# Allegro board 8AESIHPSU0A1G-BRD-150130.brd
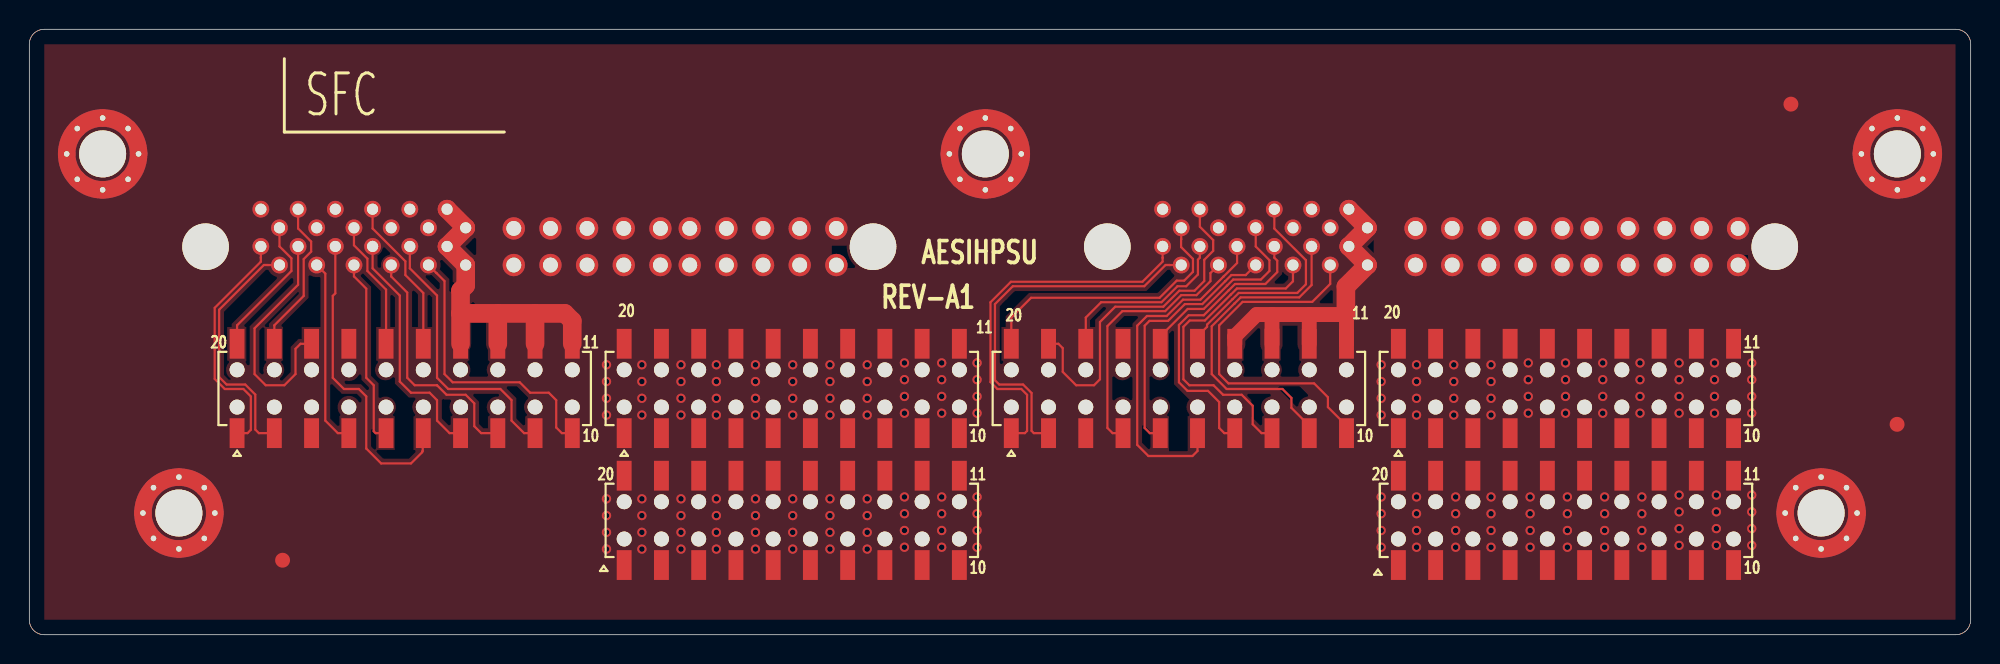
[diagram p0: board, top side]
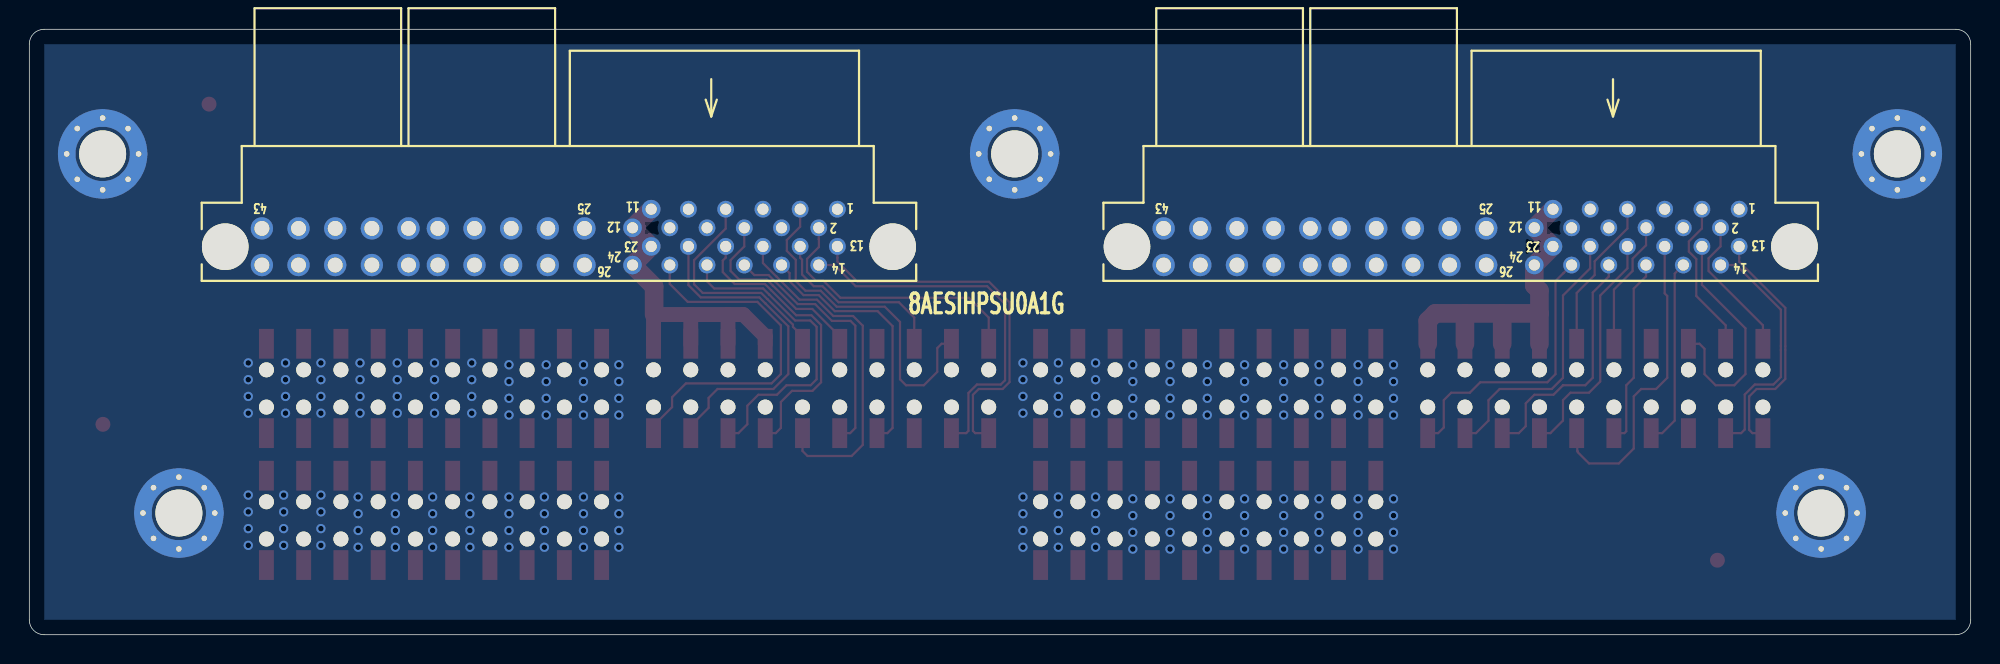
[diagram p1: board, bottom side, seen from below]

Outline 132.4 x 41.3 mm; copper layers: TOP, L2_GND1, L3_GND2, BOTTOM. Coordinates in mm from the lower left corner of the outline.
Outline path: 0,40.3 0,1 arc(0.29,0.29) 1,0 131.4,0 arc(132.11,0.29) 132.4,1 132.4,40.3 arc(132.11,41.01) 131.4,41.3 1,41.3 arc(0.29,41.01) 0,40.3

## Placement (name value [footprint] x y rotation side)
A1  3.5mm_8via  [A126_JNPR]  10.2 8.3 0 top
A2  3.5mm_8via  [A126_JNPR]  65.2 32.8 0 top
A3  3.5mm_8via  [A126_JNPR]  122.2 8.3 0 top
A4  3.5mm_8via  [A126_JNPR]  5 32.8 0 top
A5  3.5mm_8via  [A126_JNPR]  127.4 32.8 0 top
B1  Optics  [B]  17.27 5.08 0 top
B2  Optics  [B]  120.14 36.2 0 top
B3  Optics  [B]  127.38 14.35 0 top
JP1  2135_210MG0CUNT1  [IC_JP2X10_2P54_SMD]  14.17 15.53 0 top
JP2  2135_210MG0CUNT1  [IC_JP2X10_2P54_SMD]  40.57 15.53 0 top
JP3  2135_210MG0CUNT1  [IC_JP2X10_2P54_SMD]  66.97 15.53 0 top
JP4  2135_210MG0CUNT1  [IC_JP2X10_2P54_SMD]  93.37 15.53 0 top
JP5  2135_210MG0CUNT1  [IC_JP2X10_2P54_SMD]  40.57 6.53 0 top
JP6  2135_210MG0CUNT1  [IC_JP2X10_2P54_SMD]  93.37 6.53 0 top
NOREF  -  []  2.66 3.3 0 top
NOREF#2  -  []  0 0 0 top
NOREF#3  ***  []  23.21 2.18 0 top
NOREF#4  -  []  17.39 34.29 0 top
NOREF#5  -  []  58.79 21.84 0 top
NOREF#6  -  []  140.79 48.51 0 top
P1  SD45984_4343  [SD45984_4343_JNPR]  119.04 26.47 0 bottom
P2  SD45984_4343  [SD45984_4343_JNPR]  57.54 26.47 0 bottom

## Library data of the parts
A1-A5 = SCREW HOLE_6: Tolerance: ***; User Part Number: ***; room: SCREW
B1-B3 = Optics_solder_0: Tolerance: ***; User Part Number: ***
JP1-JP6 = HEADER_0: Tolerance: ***; User Part Number: ***
P1 P2 = SD45984_0: Tolerance: ***; User Part Number: ***

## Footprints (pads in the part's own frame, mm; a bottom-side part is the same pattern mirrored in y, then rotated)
A126_JNPR
  round 3.2 hole 3.2 unplated: (0,0)
  round 1.194 hole 0.381: 2(1.732,1.732) 3(-1.732,1.732) 4(-1.732,-1.732) 5(1.732,-1.732) 6(0,2.451) 7(0,-2.451) 8(-2.451,0) 9(2.451,0)
B
  round 1.016 smd: 1(0,0)
IC_JP2X10_2P54_SMD
  round 1.016 hole 1.016 unplated: (0,2.54) (0,0) (2.54,2.54) (2.54,0) (5.08,2.54) (5.08,0) (7.62,2.54) (7.62,0) (10.16,2.54) (10.16,0) (12.7,2.54) (12.7,0) (15.24,2.54) (15.24,0) (17.78,2.54) (17.78,0) (20.32,2.54) (20.32,0) (22.86,2.54) (22.86,0)
  rect 1.016x2.032 smd: 1(0,-1.778) 2(2.54,-1.778) 3(5.08,-1.778) 4(7.62,-1.778) 5(10.16,-1.778) 6(12.7,-1.778) 7(15.24,-1.778) 8(17.78,-1.778) 9(20.32,-1.778) 10(22.86,-1.778) 11(22.86,4.318) 12(20.32,4.318) 13(17.78,4.318) 14(15.24,4.318) 15(12.7,4.318) 16(10.16,4.318) 17(7.62,4.318) 18(5.08,4.318) 19(2.54,4.318) 20(0,4.318)
SD45984_4343_JNPR
  round 3.175 hole 3.175 unplated: (-45.52,0) (0,0)
  round 1.143 hole 0.762: 1(-41.75,-2.56) 2(-40.48,-1.29) 3(-39.21,-2.56) 4(-37.94,-1.29) 5(-36.67,-2.56) 6(-35.4,-1.29) 7(-34.13,-2.56) 8(-32.86,-1.29) 9(-31.59,-2.56) 10(-30.32,-1.29) 13(-41.75,-0.02) 14(-40.48,1.25) 15(-39.21,-0.02) 16(-37.94,1.25) 17(-36.67,-0.02) 18(-35.4,1.25) 19(-34.13,-0.02) 20(-32.86,1.25) 21(-31.59,-0.02) 22(-30.32,1.25)
  round 1.27 hole 0.762: 11(-29.05,-2.56) 12(-27.78,-1.29) 23(-29.05,-0.02) 24(-27.78,1.25)
  round 1.524 hole 1.016: 25(-24.5,-1.25) 26(-24.5,1.25) 27(-22,-1.25) 28(-22,1.25) 29(-19.5,-1.25) 30(-19.5,1.25) 31(-17,-1.25) 32(-17,1.25) 33(-14.5,-1.25) 34(-14.5,1.25) 35(-12.5,-1.25) 36(-12.5,1.25) 37(-10,-1.25) 38(-10,1.25) 39(-7.5,-1.25) 40(-7.5,1.25) 41(-5,-1.25) 42(-5,1.25) 43(-2.5,-1.25) 44(-2.5,1.25)

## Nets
GND: A1.2 A1.3 A1.4 A1.5 A1.6 A1.7 A1.8 A1.9 A2.2 A2.3 A2.4 A2.5 A2.6 A2.7 A2.8 A2.9 A3.2 A3.3 A3.4 A3.5 A3.6 A3.7 A3.8 A3.9 A4.2 A4.3 A4.4 A4.5 A4.6 A4.7 A4.8 A4.9 A5.2 A5.3 A5.4 A5.5 A5.6 A5.7 A5.8 A5.9 JP1.3 JP3.3 JP5.1 JP5.2 JP5.3 JP5.4 JP5.5 JP5.6 JP5.7 JP5.8 JP5.9 JP5.10 JP5.11 JP5.12 JP5.13 JP5.14 JP5.15 JP5.16 JP5.17 JP5.18 JP5.19 JP5.20 JP6.1 JP6.2 JP6.3 JP6.4 JP6.5 JP6.6 JP6.7 JP6.8 JP6.9 JP6.10 JP6.11 JP6.12 JP6.13 JP6.14 JP6.15 JP6.16 JP6.17 JP6.18 JP6.19 JP6.20 P1.25 P1.27 P1.29 P1.31 P1.33 P1.35 P1.37 P1.39 P1.41 P1.43 P2.25 P2.27 P2.29 P2.31 P2.33 P2.35 P2.37 P2.39 P2.41 P2.43
PSU0_12V: JP4.1 JP4.2 JP4.3 JP4.4 JP4.5 JP4.6 JP4.7 JP4.8 JP4.9 JP4.10 JP4.11 JP4.12 JP4.13 JP4.14 JP4.15 JP4.16 JP4.17 JP4.18 JP4.19 JP4.20 P1.26 P1.28 P1.30 P1.32 P1.34 P1.36 P1.38 P1.40 P1.42 P1.44
PSU0_+5V_STBY: JP3.11 JP3.12 JP3.13 JP3.14 P1.11 P1.12 P1.23 P1.24
PSU0_+12V_CURRENT_SHARE: JP3.18 P1.15
PSU0_+12V_RTN_SENCE: JP3.2 P1.14
PSU0_+12V_SENSE: JP3.1 P1.13
PSU0_+ PS_KILL: JP3.7 P1.19
PSU0_A0: JP3.19 P1.3
PSU0_A1: JP3.10 P1.22
PSU0_ACOK/H: JP3.15 P1.7
PSU0_EEPROM_WP: JP3.16 P1.6
PSU0_PRESENT: JP3.20 P1.2
PSU0_PSON/L: JP3.8 P1.20
PSU0_PW_OK: JP3.9 P1.21
PSU0_SCL: JP3.5 P1.18
PSU0_SDA: JP3.6 P1.17
PSU0_SMB_ALERT: JP3.4 P1.16
PSU1_12V: JP2.1 JP2.2 JP2.3 JP2.4 JP2.5 JP2.6 JP2.7 JP2.8 JP2.9 JP2.10 JP2.11 JP2.12 JP2.13 JP2.14 JP2.15 JP2.16 JP2.17 JP2.18 JP2.19 JP2.20 P2.26 P2.28 P2.30 P2.32 P2.34 P2.36 P2.38 P2.40 P2.42 P2.44
PSU1_+5V_STBY: JP1.11 JP1.12 JP1.13 JP1.14 P2.11 P2.12 P2.23 P2.24
PSU1_+12V_CURRENT_SHARE: JP1.18 P2.15
PSU1_+12V_RTN_SENCE: JP1.2 P2.14
PSU1_+12V_SENSE: JP1.1 P2.13
PSU1_+ PS_KILL: JP1.7 P2.19
PSU1_A0: JP1.19 P2.3
PSU1_A1: JP1.10 P2.22
PSU1_ACOK/H: JP1.15 P2.7
PSU1_EEPROM_WP: JP1.16 P2.6
PSU1_PRESENT: JP1.20 P2.2
PSU1_PSON/L: JP1.8 P2.20
PSU1_PW_OK: JP1.9 P2.21
PSU1_SCL: JP1.5 P2.18
PSU1_SDA: JP1.6 P2.17
PSU1_SMB_ALERT: JP1.4 P2.16

Pads without a net: B1 1; B2 1; B3 1; JP1 17; JP3 17; P1 1 4 5 8 9 10; P2 1 4 5 8 9 10

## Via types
v1: diameter 0.635, hole 0.381, TOP to BOTTOM, 176 vias

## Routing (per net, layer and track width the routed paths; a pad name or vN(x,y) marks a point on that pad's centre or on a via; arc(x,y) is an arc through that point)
GND:
  vias: v1(39.36,9.27) v1(39.36,8.13) v1(39.36,6.98) v1(39.36,5.84) v1(41.78,9.27) v1(41.78,8.13) v1(41.78,6.98) v1(41.78,5.84) v1(44.44,9.27) v1(44.44,8.13) v1(44.44,6.98) v1(44.44,5.84) v1(46.86,9.27) v1(46.86,8.13) v1(46.86,6.98) v1(46.86,5.84) v1(49.52,9.27) v1(49.52,8.13) v1(49.52,6.98) v1(49.52,5.84) v1(52.06,9.27) v1(52.06,8.13) v1(52.06,6.98) v1(52.06,5.84) v1(54.6,9.27) v1(54.6,8.13) v1(54.6,6.98) v1(54.6,5.84) v1(57.14,9.27) v1(57.14,8.13) v1(57.14,6.98) v1(57.14,5.84) v1(59.68,9.4) v1(59.68,8.25) v1(59.68,7.11) v1(59.68,5.97) v1(62.22,9.4) v1(62.22,8.25) v1(62.22,7.11) v1(62.22,5.97) v1(64.64,9.4) v1(64.64,8.25) v1(64.64,7.11) v1(64.64,5.97) v1(92.19,9.4) v1(92.19,8.25) v1(92.19,7.11) v1(92.19,5.97) v1(94.61,9.4) v1(94.61,8.25) v1(94.61,7.11) v1(94.61,5.97) v1(97.27,9.4) v1(97.27,8.25) v1(97.27,7.11) v1(97.27,5.97) v1(99.69,9.4) v1(99.69,8.25) v1(99.69,7.11) v1(99.69,5.97) v1(102.35,9.4) v1(102.35,8.25) v1(102.35,7.11) v1(102.35,5.97) v1(104.89,9.4) v1(104.89,8.25) v1(104.89,7.11) v1(104.89,5.97) v1(107.43,9.4) v1(107.43,8.25) v1(107.43,7.11) v1(107.43,5.97) v1(109.97,9.4) v1(109.97,8.25) v1(109.97,7.11) v1(109.97,5.97) v1(112.51,9.52) v1(112.51,8.38) v1(112.51,7.24) v1(112.51,6.09) v1(115.05,9.52) v1(115.05,8.38) v1(115.05,7.24) v1(115.05,6.09) v1(117.47,9.52) v1(117.47,8.38) v1(117.47,7.24) v1(117.47,6.09)
PSU0_12V:
  vias: v1(92.19,18.41) v1(92.19,17.27) v1(92.19,16.13) v1(92.19,14.98) v1(94.61,18.41) v1(94.61,17.27) v1(94.61,16.13) v1(94.61,14.98) v1(97.15,18.41) v1(97.15,17.27) v1(97.15,16.13) v1(97.15,14.98) v1(99.69,18.41) v1(99.69,17.27) v1(99.69,16.13) v1(99.69,14.98) v1(102.23,18.54) v1(102.23,17.4) v1(102.23,16.25) v1(102.23,15.11) v1(104.77,18.54) v1(104.77,17.4) v1(104.77,16.25) v1(104.77,15.11) v1(107.31,18.54) v1(107.31,17.4) v1(107.31,16.25) v1(107.31,15.11) v1(109.85,18.54) v1(109.85,17.4) v1(109.85,16.25) v1(109.85,15.11) v1(112.51,18.54) v1(112.51,17.4) v1(112.51,16.25) v1(112.51,15.11) v1(114.93,18.54) v1(114.93,17.4) v1(114.93,16.25) v1(114.93,15.11) v1(117.47,18.54) v1(117.47,17.4) v1(117.47,16.25) v1(117.47,15.11)
PSU0_+5V_STBY: length 24.1
  TOP w1.016: JP3.14 82.21,20.35 83.7,21.84 84.75,21.84 ; JP3.11 89.83,21.84 87.29,21.84 ; JP3.12 87.29,21.84 ; 87.29,21.84 84.75,21.84 ; 84.75,21.84 JP3.13
  TOP w1.27: 89.79,21.84 89.79,23.75 91.26,25.22 P1.24 P1.23 P1.12 P1.11
PSU0_+12V_CURRENT_SHARE: length 12.6
  TOP w0.152: JP3.18 72.05,21.64 73.09,22.68 77.21,22.68 78.3,23.77 78.9,23.77 79.7,24.57 79.7,25.58 79.83,25.72 P1.15
PSU0_+12V_RTN_SENCE: length 25.7
  TOP w0.152: P1.14 77.79,25.22 77.78,25.22 77.49,25.22 76.04,23.77 67.07,23.77 65.86,22.55 65.86,17.36 66.15,17.07 67.78,17.07 68.35,16.49 68.35,13.9 68.51,13.75 JP3.2
PSU0_+12V_SENSE: length 25.8
  TOP w0.152: JP3.1 67.89,13.75 68.05,13.9 68.05,16.36 67.65,16.76 66.02,16.76 65.55,17.23 65.55,22.68 66.95,24.08 75.91,24.08 77.29,25.45 77.29,25.71 P1.13
PSU0_+ PS_KILL: length 20.2
  TOP w0.152: JP3.7 81.5,13.75 81.15,14.1 81.15,15.87 80.38,16.63 78.99,16.63 78.4,17.22 78.4,21.13 79.06,21.79 80.1,21.79 81.81,23.5 82.23,23.92 84.3,23.92 85.11,24.74 85.11,25.52 84.91,25.72 P1.19
PSU0_A0: length 23.5
  TOP w0.152: P1.3 79.83,27.83 80.74,26.92 80.74,26.19 80.13,25.58 80.13,24.13 79.47,23.47 78.43,23.47 77.34,22.38 74.06,22.38 73.02,21.33 73.02,17.42 72.61,17.02 71.39,17.02 70.48,17.93 70.48,19.55 70.18,19.85 69.51,19.85 JP3.19
PSU0_A1: length 24.4
  TOP w0.152: P1.22 88.72,23.93 87.5,22.71 82.75,22.71 81.15,21.11 81.15,17.78 81.78,17.14 87.62,17.14 88.56,16.2 88.56,15.53 89.83,14.26 JP3.10
PSU0_ACOK/H: length 15.5
  TOP w0.152: P1.7 84.91,27.7 87.06,25.55 87.06,23.91 86.47,23.32 82.48,23.32 82.06,22.89 82.06,22.89 80.32,21.15 80.32,21.01 79.67,20.35 JP3.15
PSU0_EEPROM_WP: length 13.1
  TOP w0.152: JP3.16 77.13,20.35 79,22.22 80.1,22.22 81.68,23.81 81.68,23.81 82.11,24.23 83.99,24.23 84.57,24.81 84.57,25.55 83.64,26.49 P1.6
PSU0_PRESENT: length 18.8
  TOP w0.152: P1.2 78.56,26.99 78.55,26.98 78.55,26.44 79.36,25.63 79.36,24.76 78.76,24.15 78.25,24.15 77.08,22.98 68.32,22.98 66.97,21.64 JP3.20
PSU0_PSON/L: length 21.8
  TOP w0.152: P1.20 86.18,24.11 85.69,23.62 82.36,23.62 81.94,23.2 81.94,23.2 80.17,21.44 79.14,21.44 78.71,21 78.71,17.42 79.11,17.02 80.76,17.02 81.41,16.37 82.68,16.37 83.43,15.62 83.43,14.36 84.04,13.75 JP3.8
PSU0_PW_OK: length 22.9
  TOP w0.152: JP3.9 87.29,14.26 86.07,15.47 86.07,16.15 85.46,16.76 81.65,16.76 80.64,17.78 80.64,21.04 82.19,22.59 82.19,22.59 82.61,23.01 86.61,23.01 87.45,23.85 P1.21
PSU0_SCL: length 17.5
  TOP w0.152: P1.18 82.96,24.53 81.98,24.53 81.56,24.11 81.56,24.11 80,22.55 78.81,22.55 77.67,21.41 76.4,21.41 76.07,21.08 76.07,14.1 76.42,13.75 JP3.5
PSU0_SDA: length 23.6
  TOP w0.152: JP3.6 79.67,12.53 79.33,12.19 76.32,12.19 75.56,12.95 75.56,21.08 76.22,21.74 77.56,21.74 78.68,22.86 79.87,22.86 81.43,24.42 81.43,24.42 82.37,25.36 P1.17
PSU0_SMB_ALERT: length 17.8
  TOP w0.152: P1.16 81.1,25.22 80.55,24.67 80.55,24.12 79.6,23.16 78.56,23.16 77.46,22.07 74.54,22.07 73.53,21.05 73.53,14.1 73.88,13.75 JP3.4
PSU1_12V:
  vias: v1(39.36,18.41) v1(39.36,17.27) v1(39.36,16.13) v1(39.36,14.98) v1(41.78,18.41) v1(41.78,17.27) v1(41.78,16.13) v1(41.78,14.98) v1(44.44,18.41) v1(44.44,17.27) v1(44.44,16.13) v1(44.44,14.98) v1(46.86,18.41) v1(46.86,17.27) v1(46.86,16.13) v1(46.86,14.98) v1(49.52,18.41) v1(49.52,17.27) v1(49.52,16.13) v1(49.52,14.98) v1(52.06,18.41) v1(52.06,17.27) v1(52.06,16.13) v1(52.06,14.98) v1(54.6,18.41) v1(54.6,17.27) v1(54.6,16.13) v1(54.6,14.98) v1(57.14,18.41) v1(57.14,17.27) v1(57.14,16.13) v1(57.14,14.98) v1(59.68,18.54) v1(59.68,17.4) v1(59.68,16.25) v1(59.68,15.11) v1(62.22,18.54) v1(62.22,17.4) v1(62.22,16.25) v1(62.22,15.11) v1(64.64,18.54) v1(64.64,17.4) v1(64.64,16.25) v1(64.64,15.11)
PSU1_+5V_STBY: length 24.4
  TOP w1.27: 34.49,21.92 36.52,21.92 37.03,21.41 JP1.11 ; 34.49,21.92 31.95,21.92 ; 34.49,21.92 JP1.12 ; P2.11 P2.12 P2.23 P2.24 29.76,23.82 29.41,23.47 29.41,21.92 ; 31.95,21.92 JP1.13 ; 31.95,21.92 29.41,21.92 ; JP1.14 29.41,21.92
PSU1_+12V_CURRENT_SHARE: length 16.3
  TOP w0.152: JP1.18 18.5,19.85 18.15,19.5 18.15,17.78 17.39,17.02 16.12,17.02 15.36,17.78 15.36,20.9 18.33,23.87 P2.15
PSU1_+12V_RTN_SENCE: length 16.7
  TOP w0.152: JP1.2 15.65,13.75 15.41,13.99 15.41,16.38 14.72,17.07 13.45,17.07 12.95,17.57 12.95,19.43 12.95,19.68 12.95,22.17 15.99,25.22 16.28,25.22 16.29,25.22 P2.14
PSU1_+12V_SENSE: length 16.6
  TOP w0.152: JP1.1 14.88,13.75 15.11,13.97 15.11,16.25 14.6,16.76 13.33,16.76 12.64,17.45 12.64,19.43 12.64,19.68 12.64,22.3 15.79,25.45 15.79,25.71 15.79,25.71 P2.13
PSU1_+ PS_KILL: length 16.4
  TOP w0.152: JP1.7 28.66,13.75 27.81,14.6 27.81,16 27.3,16.51 26.03,16.51 25.27,17.27 25.27,23.14 23.41,24.99 P2.19
PSU1_A0: length 10.6
  TOP w0.152: P2.3 18.33,27.71 19.22,26.82 19.22,26.13 18.71,25.63 18.71,23.11 16.71,21.11 JP1.19
PSU1_A1: length 19.4
  TOP w0.152: JP1.10 36.32,13.75 35.93,14.13 35.93,16 35.43,16.51 34.16,16.51 33.44,17.22 28.87,17.22 28.31,17.78 28.31,24.13 27.77,24.67 27.77,24.67 P2.22
PSU1_ACOK/H: length 10.6
  TOP w0.152: P2.7 23.41,27.71 25.65,25.48 25.65,24.54 26.87,23.31 JP1.15
PSU1_EEPROM_WP: length 8.8
  TOP w0.152: P2.6 22.14,26.57 23.06,25.65 23.06,24.81 24.33,23.54 JP1.16
PSU1_PRESENT: length 9.8
  TOP w0.152: JP1.20 14.17,21.11 17.87,24.81 17.87,25.68 17.06,26.49 P2.2
PSU1_PSON/L: length 16.8
  TOP w0.152: P2.20 24.68,24.43 25.77,23.34 25.77,17.52 26.28,17.02 27.81,17.02 28.45,16.37 29.76,16.37 30.35,15.78 30.35,14.22 30.82,13.75 JP1.8
PSU1_PW_OK: length 18.8
  TOP w0.152: P2.21 25.95,24.99 27.81,23.14 27.81,17.52 28.57,16.76 32.12,16.76 32.89,16 32.89,14.6 33.74,13.75 JP1.9
PSU1_SCL: length 12.8
  TOP w0.152: JP1.5 23.62,13.75 23.49,13.88 23.49,17.02 22.98,17.52 22.98,23.61 22.14,24.45 P2.18
PSU1_SDA: length 21.3
  TOP w0.152: P2.17 20.87,23.29 20.69,23.11 20.69,17.52 21.46,16.76 22.47,16.76 22.98,16.25 22.98,12.7 24,11.68 26.03,11.68 26.79,12.44 26.79,12.49 26.83,12.53 26.83,12.98 26.87,13.02 JP1.6
PSU1_SMB_ALERT: length 12.8
  TOP w0.152: P2.16 19.6,25.22 20.19,24.63 20.19,14.6 21.04,13.75 JP1.4

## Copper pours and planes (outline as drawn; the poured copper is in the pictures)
GND on TOP (solid shape): outline of 222 points within 1.95,29.75 8.05,35.85
GND on TOP (solid shape): outline of 222 points within 7.15,5.25 13.25,11.35
GND on TOP (solid shape): outline of 222 points within 62.15,29.75 68.25,35.85
GND on TOP (solid shape): outline of 222 points within 119.15,5.25 125.25,11.35
GND on TOP (solid shape): outline of 222 points within 124.35,29.75 130.45,35.85
GND on BOTTOM (solid shape): outline of 222 points within 1.95,29.75 8.05,35.85
GND on BOTTOM (solid shape): outline of 222 points within 7.15,5.25 13.25,11.35
GND on BOTTOM (solid shape): outline of 222 points within 62.15,29.75 68.25,35.85
GND on BOTTOM (solid shape): outline of 222 points within 119.15,5.25 125.25,11.35
GND on BOTTOM (solid shape): outline of 222 points within 124.35,29.75 130.45,35.85
GND on TOP: 131.37,40.28 131.37,1.02 1.02,1.02 1.02,40.28 ; 35 cut-outs
GND on BOTTOM: 1.02,1.02 1.02,40.28 131.38,40.28 131.38,1.02 ; 3 cut-outs
GND on L2_GND1, L3_GND2: 1.02,1.02 1.02,40.28 131.38,40.28 131.38,1.02
PSU0_12V on TOP, BOTTOM: 91.69,28.17 91.69,13.59 92.58,12.7 118.61,12.7 119.37,13.46 119.37,29.21 117.34,31.24 94.76,31.24 ; 1 cut-out
PSU1_12V on TOP, BOTTOM: 39.24,12.44 38.73,12.95 38.73,22.86 37.71,23.87 31.74,23.87 30.73,24.89 30.73,31.87 31.11,32.26 55.75,32.26 65.14,22.86 65.14,12.95 64.64,12.44 ; 1 cut-out

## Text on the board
Ref Des/Silkscreen Top: REV-A1 | AESIHPSU
User.45: FIGURE | SIZE | 15.0 | 30.0 | 40.0 | 125.0 | 126.0 | DRILL CHART: TOP to BOTTOM | ALL UNITS ARE IN MILS | TOLERANCE | +3.0/-3.0 | +2.0/-2.0 | PLATED | NON-PLATED | QTY | 216 | 48 | 40 | 120 | 4 | 5
